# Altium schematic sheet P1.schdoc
size 420 x 297 mm; Symbol: Drawing-Symbol_A4; Company: 嘉立创EDA; Version: V1.0; Page Size: A4; @Project Name: SmartSleeve; @Update Date: 2026-07-03; @Create Date: 2026-07-03; Device: Drawing-Symbol_A4; @Board Name: Board1; @Page Name: P1; @Create Time: 23:50:37; @Page Count: 1; @Page No: 1; @Schematic Name: Schematic1; @Update Time: 23:50:37; @Assembly Variant: Basic; Border: 1; Title Block Position: 3; Size: A4; Width: 1655; Height: 1170; Region Start: 1; X Region Count: 6; Y Region Count: 4; Blade Width: 10
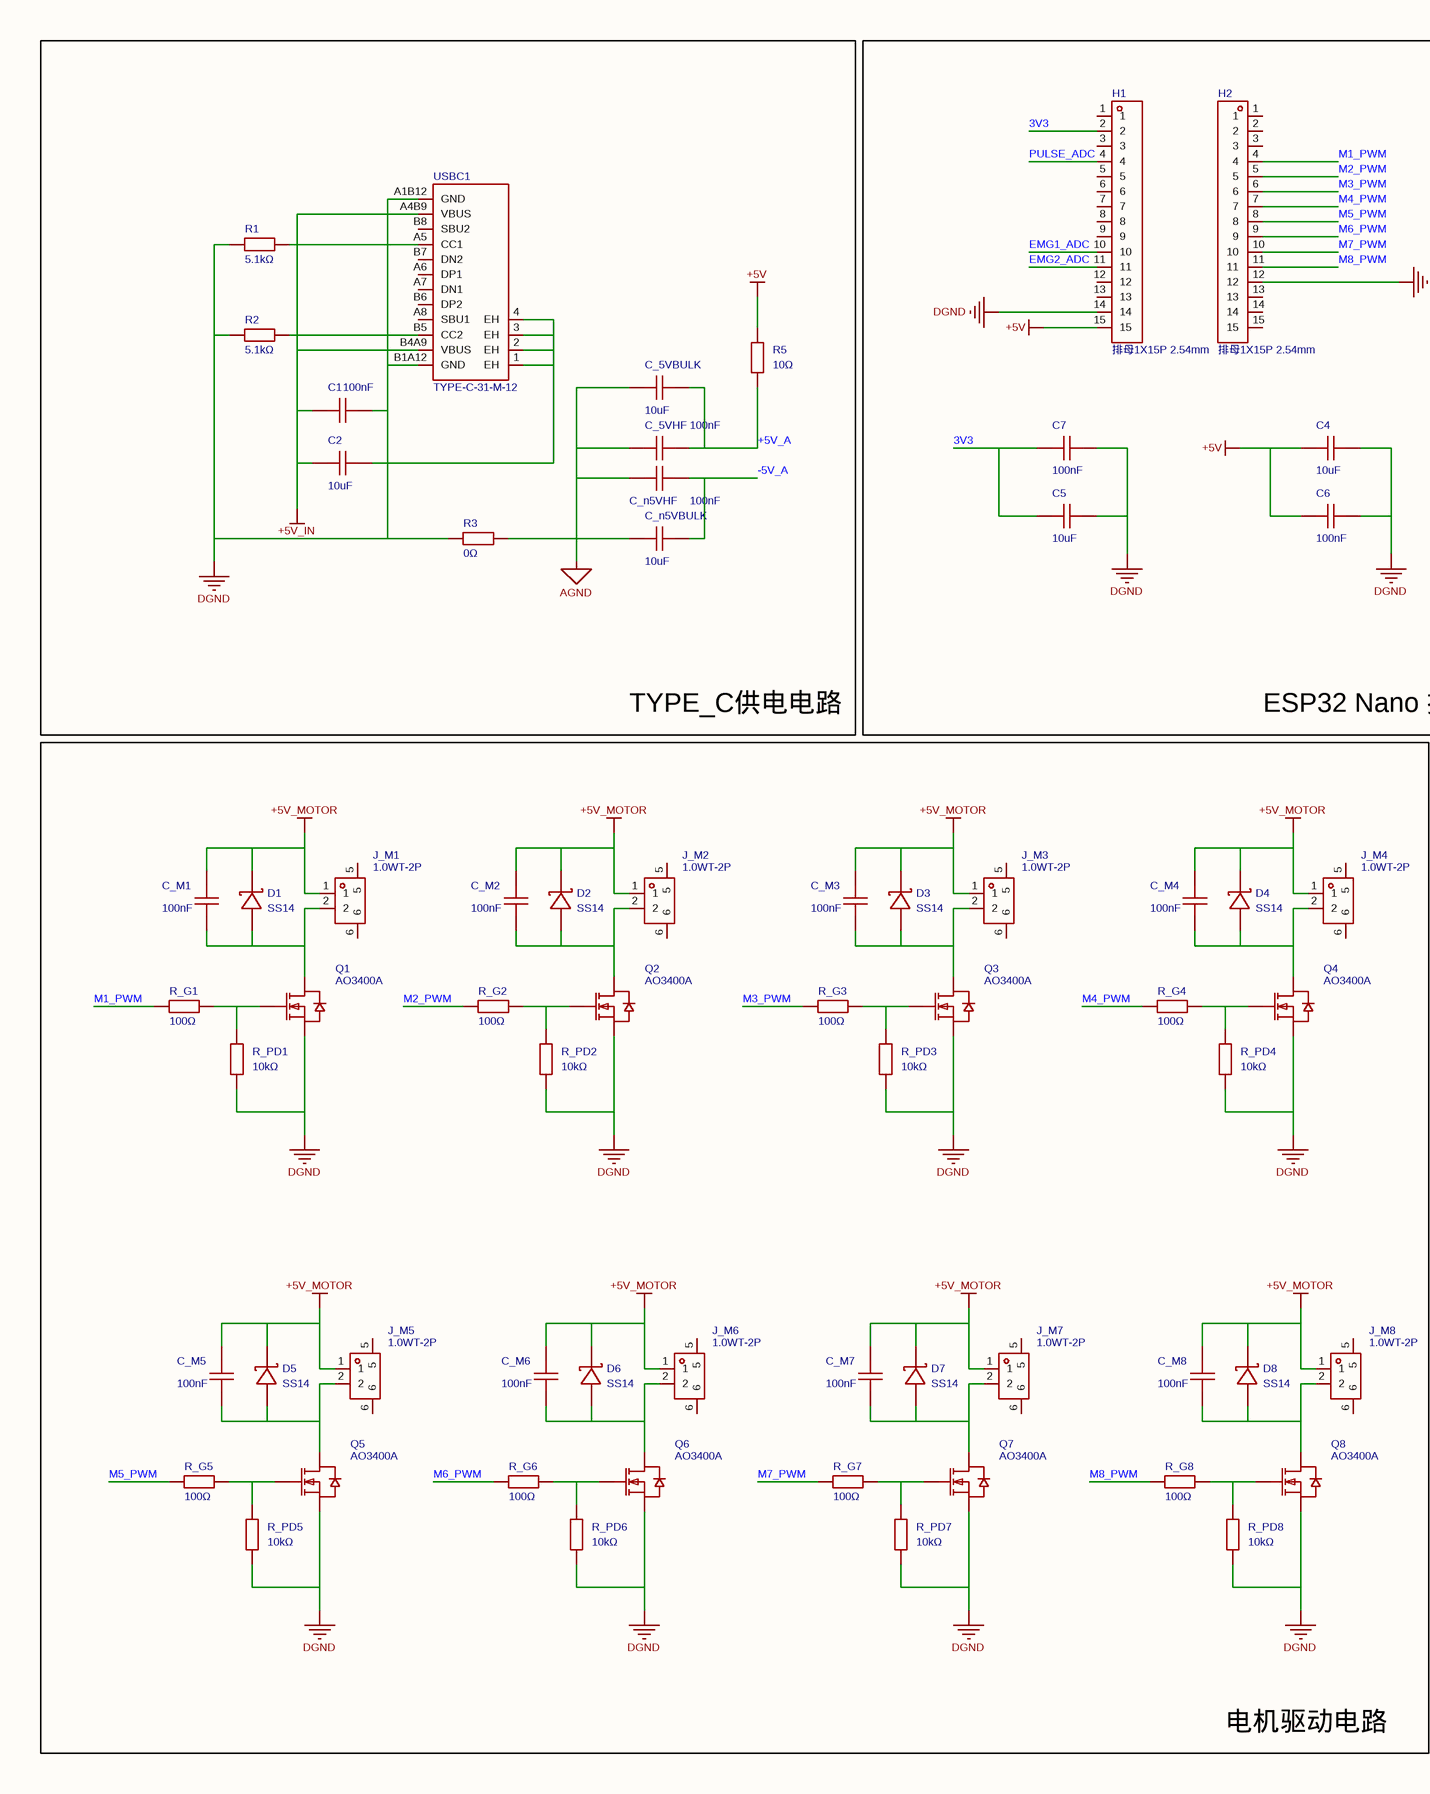
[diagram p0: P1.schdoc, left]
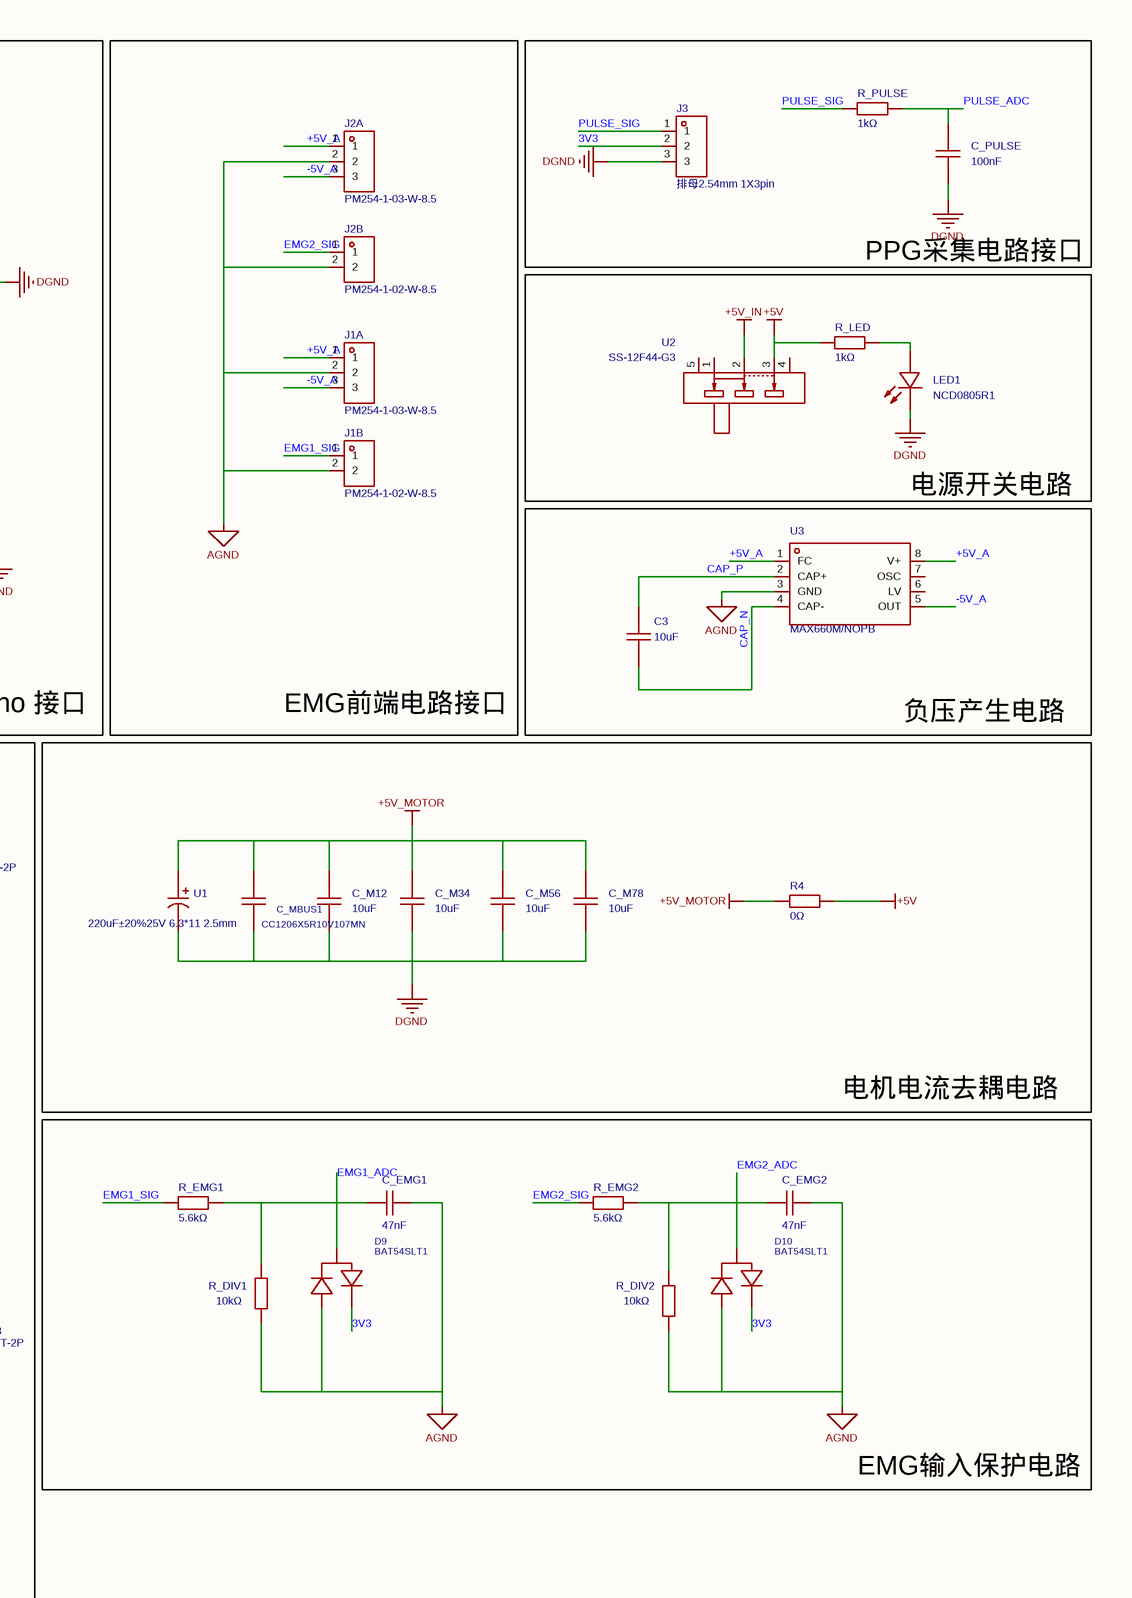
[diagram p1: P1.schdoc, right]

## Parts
C1  100nF  [C0805]
C2  10uF  [C0805]
C3  10uF  [C0805]
C4  10uF  [C0805]
C5  10uF  [C0805]
C6  100nF  [C0805]
C7  100nF  [C0805]
C_5VBULK  10uF  [C0805]
C_5VHF  100nF  [C0805]
C_EMG1  47nF  [C0805]
C_EMG2  47nF  [C0805]
C_M1  100nF  [C0805]
C_M2  100nF  [C0805]
C_M3  100nF  [C0805]
C_M4  100nF  [C0805]
C_M5  100nF  [C0805]
C_M6  100nF  [C0805]
C_M7  100nF  [C0805]
C_M8  100nF  [C0805]
C_M12  10uF  [C0805]
C_M34  10uF  [C0805]
C_M56  10uF  [C0805]
C_M78  10uF  [C0805]
C_MBUS1  CC1206X5R10V107MN  [C1206]
C_n5VBULK  10uF  [C0805]
C_n5VHF  100nF  [C0805]
C_PULSE  100nF  [C0805]
D1  SS14  [SMA_L4.2-W2.6-LS5.0-RD_1]
D2  SS14  [SMA_L4.2-W2.6-LS5.0-RD_1]
D3  SS14  [SMA_L4.2-W2.6-LS5.0-RD_1]
D4  SS14  [SMA_L4.2-W2.6-LS5.0-RD_1]
D5  SS14  [SMA_L4.2-W2.6-LS5.0-RD_1]
D6  SS14  [SMA_L4.2-W2.6-LS5.0-RD_1]
D7  SS14  [SMA_L4.2-W2.6-LS5.0-RD_1]
D8  SS14  [SMA_L4.2-W2.6-LS5.0-RD_1]
D9  BAT54SLT1  [SOT-23-3_L2.9-W1.3-P1.90-LS2.4-BR]
D10  BAT54SLT1  [SOT-23-3_L2.9-W1.3-P1.90-LS2.4-BR]
H1  排母1X15P 2.54mm  [HDR-TH_15P-P2.54-V-F]
H2  排母1X15P 2.54mm  [HDR-TH_15P-P2.54-V-F]
J1A  PM254-1-03-W-8.5  [HDR-TH_3P-P2.54-H-F-W10.0-N]
J1B  PM254-1-02-W-8.5  [HDR-TH_2P-P2.54-H-F-W10.0-N]
J2A  PM254-1-03-W-8.5  [HDR-TH_3P-P2.54-H-F-W10.0-N]
J2B  PM254-1-02-W-8.5  [HDR-TH_2P-P2.54-H-F-W10.0-N]
J3  排母2.54mm 1X3pin  [HDR-TH_3P-P2.54_CS-1165SDIG]
J_M1  1.0WT-2P  [CONN-SMD_2P-P1.00-WT]
J_M2  1.0WT-2P  [CONN-SMD_2P-P1.00-WT]
J_M3  1.0WT-2P  [CONN-SMD_2P-P1.00-WT]
J_M4  1.0WT-2P  [CONN-SMD_2P-P1.00-WT]
J_M5  1.0WT-2P  [CONN-SMD_2P-P1.00-WT]
J_M6  1.0WT-2P  [CONN-SMD_2P-P1.00-WT]
J_M7  1.0WT-2P  [CONN-SMD_2P-P1.00-WT]
J_M8  1.0WT-2P  [CONN-SMD_2P-P1.00-WT]
LED1  NCD0805R1  [LED0805-RD]
Q1  AO3400A  [SOT-23-3_L2.9-W1.3-P1.90-LS2.4-BR]
Q2  AO3400A  [SOT-23-3_L2.9-W1.3-P1.90-LS2.4-BR]
Q3  AO3400A  [SOT-23-3_L2.9-W1.3-P1.90-LS2.4-BR]
Q4  AO3400A  [SOT-23-3_L2.9-W1.3-P1.90-LS2.4-BR]
Q5  AO3400A  [SOT-23-3_L2.9-W1.3-P1.90-LS2.4-BR]
Q6  AO3400A  [SOT-23-3_L2.9-W1.3-P1.90-LS2.4-BR]
Q7  AO3400A  [SOT-23-3_L2.9-W1.3-P1.90-LS2.4-BR]
Q8  AO3400A  [SOT-23-3_L2.9-W1.3-P1.90-LS2.4-BR]
R1  5.1kΩ  [R0805]
R2  5.1kΩ  [R0805]
R3  0Ω  [R0805]
R4  0Ω  [R1206]
R5  10Ω  [R0805_NEW]
R_DIV1  10kΩ  [R0805]
R_DIV2  10kΩ  [R0805]
R_EMG1  5.6kΩ  [R0805]
R_EMG2  5.6kΩ  [R0805]
R_G1  100Ω  [R0805]
R_G2  100Ω  [R0805]
R_G3  100Ω  [R0805]
R_G4  100Ω  [R0805]
R_G5  100Ω  [R0805]
R_G6  100Ω  [R0805]
R_G7  100Ω  [R0805]
R_G8  100Ω  [R0805]
R_LED  1kΩ  [R0805]
R_PD1  10kΩ  [R0805]
R_PD2  10kΩ  [R0805]
R_PD3  10kΩ  [R0805]
R_PD4  10kΩ  [R0805]
R_PD5  10kΩ  [R0805]
R_PD6  10kΩ  [R0805]
R_PD7  10kΩ  [R0805]
R_PD8  10kΩ  [R0805]
R_PULSE  1kΩ  [R0805]
U1  220uF±20%25V 6.3*11 2.5mm  [CAP-TH_BD6.3-P2.50-D0.5-FD]
U2  SS-12F44-G3  [SW-TH_SS-12F44-G5_C2998807]
U3  MAX660M/NOPB  [SOIC-8_L5.0-W4.0-P1.27-LS6.1-BL]
USBC1  TYPE-C-31-M-12  [USB-C_SMD-TYPE-C-31-M-12_1]

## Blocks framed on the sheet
TYPE_C供电电路: C1 C2 C_5VBULK C_5VHF C_n5VBULK C_n5VHF R1-R3 R5 USBC1
ESP32 Nano 接口: C4-C7 H1 H2
EMG前端电路接口: J1A J1B J2A J2B
PPG采集电路接口: C_PULSE J3 R_PULSE
电源开关电路: LED1 R_LED U2
负压产生电路: C3 U3
电机驱动电路: C_M1-C_M8 D1-D8 J_M1-J_M8 Q1-Q8 R_G1-R_G8 R_PD1-R_PD8
电机电流去耦电路: C_M12 C_M34 C_M56 C_M78 C_MBUS1 R4 U1
EMG输入保护电路: C_EMG1 C_EMG2 D9 D10 R_DIV1 R_DIV2 R_EMG1 R_EMG2

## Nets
+5V: C4.1 C6.1 H1.15 R4.2 R5.1 R_LED.2 U2.3
+5V_IN: C1.1 C2.1 U2.2 USBC1.A4B9(VBUS) USBC1.B4A9(VBUS)
+5V_MOTOR: C_M1.2 C_M2.2 C_M3.2 C_M4.2 C_M5.2 C_M6.2 C_M7.2 C_M8.2 C_M12.2 C_M34.2 C_M56.2 C_M78.2 C_MBUS1.2 D1.1(K) D2.1(K) D3.1(K) D4.1(K) D5.1(K) D6.1(K) D7.1(K) D8.1(K) J_M1.1 J_M2.1 J_M3.1 J_M4.1 J_M5.1 J_M6.1 J_M7.1 J_M8.1 R4.1 U1.1
AGND: C_5VBULK.1 C_5VHF.1 C_EMG1.2 C_EMG2.2 C_n5VBULK.1 C_n5VHF.1 D9.1(A) D10.1(A) J1A.2 J1B.2 J2A.2 J2B.2 R3.2 R_DIV1.1 R_DIV2.1 U3.3(GND)
DGND: C1.2 C2.2 C4.2 C5.2 C6.2 C7.2 C_M12.1 C_M34.1 C_M56.1 C_M78.1 C_MBUS1.1 C_PULSE.1 H1.14 H2.12 J3.3 LED1.1(-) Q1.2(S) Q2.2(S) Q3.2(S) Q4.2(S) Q5.2(S) Q6.2(S) Q7.2(S) Q8.2(S) R1.2 R2.1 R3.1 R_PD1.1 R_PD2.1 R_PD3.1 R_PD4.1 R_PD5.1 R_PD6.1 R_PD7.1 R_PD8.1 U1.2 USBC1.1(EH) USBC1.2(EH) USBC1.3(EH) USBC1.4(EH) USBC1.A1B12(GND) USBC1.B1A12(GND)
3V3: C5.1 C7.1 D9.2(C) D10.2(C) H1.2 J3.2
+5V_A: C_5VBULK.2 C_5VHF.2 J1A.1 J2A.1 R5.2 U3.1(FC) U3.8(V+)
-5V_A: C_n5VBULK.2 C_n5VHF.2 J1A.3 J2A.3 U3.5(OUT)
CAP_N: C3.2 U3.4(CAP-)
CAP_P: C3.1 U3.2(CAP+)
EMG1_ADC: C_EMG1.1 D9.3(A/C) H1.10 R_DIV1.2 R_EMG1.2
EMG1_SIG: J1B.1 R_EMG1.1
EMG2_ADC: C_EMG2.1 D10.3(A/C) H1.11 R_DIV2.2 R_EMG2.2
EMG2_SIG: J2B.1 R_EMG2.1
M1_PWM: H2.4 R_G1.1
M2_PWM: H2.5 R_G2.1
M3_PWM: H2.6 R_G3.1
M4_PWM: H2.7 R_G4.1
M5_PWM: H2.8 R_G5.1
M6_PWM: H2.9 R_G6.1
M7_PWM: H2.10 R_G7.1
M8_PWM: H2.11 R_G8.1
PULSE_ADC: C_PULSE.2 H1.4 R_PULSE.2
PULSE_SIG: J3.1 R_PULSE.1
NetC_M1_1: C_M1.1 D1.2(A) J_M1.2 Q1.3(D)
NetC_M2_1: C_M2.1 D2.2(A) J_M2.2 Q2.3(D)
NetC_M3_1: C_M3.1 D3.2(A) J_M3.2 Q3.3(D)
NetC_M4_1: C_M4.1 D4.2(A) J_M4.2 Q4.3(D)
NetC_M5_1: C_M5.1 D5.2(A) J_M5.2 Q5.3(D)
NetC_M6_1: C_M6.1 D6.2(A) J_M6.2 Q6.3(D)
NetC_M7_1: C_M7.1 D7.2(A) J_M7.2 Q7.3(D)
NetC_M8_1: C_M8.1 D8.2(A) J_M8.2 Q8.3(D)
NetLED1_2: LED1.2(+) R_LED.1
NetQ1_1: Q1.1(G) R_G1.2 R_PD1.2
NetQ2_1: Q2.1(G) R_G2.2 R_PD2.2
NetQ3_1: Q3.1(G) R_G3.2 R_PD3.2
NetQ4_1: Q4.1(G) R_G4.2 R_PD4.2
NetQ5_1: Q5.1(G) R_G5.2 R_PD5.2
NetQ6_1: Q6.1(G) R_G6.2 R_PD6.2
NetQ7_1: Q7.1(G) R_G7.2 R_PD7.2
NetQ8_1: Q8.1(G) R_G8.2 R_PD8.2
NetR1_1: R1.1 USBC1.A5(CC1)
NetR2_2: R2.2 USBC1.B5(CC2)

Not connected (* = marked no-connect by the designer): H1 1 3 5 6 7 8 9 12 13; H2 1 2 3 13 14 15; J_M1 5 6; J_M2 5 6; J_M3 5 6; J_M4 5 6; J_M5 5 6; J_M6 5 6; J_M7 5 6; J_M8 5 6; U2 1 4 5; U3 6(LV) 7(OSC); USBC1 A6(DP1) A7(DN1) A8(SBU1) B6(DP2) B7(DN2) B8(SBU2)

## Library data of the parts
C1 = GRM21BR71H104KA01L: 容值:100nF;精度:±10%;额定电压:50V;温度系数:X7R;; Manufacturer: muRata(村田); 3D Model: 1ba041120af144c991958decab20d2410819f05c4eef4c71ace90d822a990e87; 3D Model Transform: 78.74,51.181,0,0,0,0,0,0.0005,0; Tolerance: ±10%; Voltage Rating: 50V; Temperature Coefficient: X7R; AddInBom: yes; ModelName: C0805_L2.0-W1.3-H1.3
C2 = CL21A106KAYNNNE_C15850: 容值:10uF;精度:±10%;额定电压:25V;温度系数:X5R;; Manufacturer: SAMSUNG(三星); Add into BOM: yes; Tolerance: ±10%; Voltage Rating: 25V; Temperature Coefficient: X5R; 3D Model: 1ba041120af144c991958decab20d241; 3D Model Transform: 78.74,51.181,0,0,0,0,0,0.0005,0; ModelName: C0805_L2.0-W1.3-H1.3
C3-C5 C_5VBULK C_M12 C_M34 C_M56 C_M78 C_n5VBULK = CL21A106KAYNNNE_C15850: 容值:10uF;精度:±10%;额定电压:25V;温度系数:X5R;; Manufacturer: SAMSUNG(三星); 3D Model: 1ba041120af144c991958decab20d2410819f05c4eef4c71ace90d822a990e87; 3D Model Transform: 78.74,51.181,0,0,0,0,0,0.0005,0; Tolerance: ±10%; Voltage Rating: 25V; Temperature Coefficient: X5R; AddInBom: yes; ModelName: C0805_L2.0-W1.3-H1.3
C6 C7 C_5VHF C_M1-C_M8 C_n5VHF C_PULSE = CC0805KRX7R9BB104: 容值:100nF;精度:±10%;额定电压:50V;温度系数:X7R;; Manufacturer: YAGEO(国巨); 3D Model: 1ba041120af144c991958decab20d2410819f05c4eef4c71ace90d822a990e87; 3D Model Transform: 78.74,51.181,0,0,0,0,0,0.0005,0; Tolerance: ±10%; Voltage Rating: 50V; Temperature Coefficient: X7R; AddInBom: yes; ModelName: C0805_L2.0-W1.3-H1.3
C_EMG1 C_EMG2 = CL21B473KBCNNNC: 容值:47nF;精度:±10%;额定电压:50V;材质(温度系数):X7R;; Manufacturer: SAMSUNG(三星); AddInBom: yes; ModelId: 1ba041120af144c991958decab20d2410819f05c4eef4c71ace90d822a990e87; ModelName: C0805_L2.0-W1.3-H1.3; ModelTransform: 78.74,51.181,0,0,0,0,0,0.0005,0; Tolerance: ±10%; Voltage Rated: 50V; Temperature Coefficient: X7R
C_MBUS1 = CC1206X5R10V107MN: Manufacturer: TORCH(火炬); AddInBom: yes; ModelId: e4be705b945545a48e666415e3682bd80819f05c4eef4c71ace90d822a990e87; ModelName: C1206_L3.2-W1.6-H1.3; ModelTransform: 125.984,62.992,0,0,0,0,0,0,0
D1-D8 = SS14_C2480: 二极管配置:独立式;正向压降(Vf):550mV@1A;直流反向耐压(Vr):40V;整流电流:1A;; Manufacturer: MDD(辰达半导体); 3D Model: 2ad98c37c5614ad18681cbd22e4725e10819f05c4eef4c71ace90d822a990e87; 3D Model Transform: 196.85,101.181,0,0,0,0,0,0,0; Diode Configuration: 独立式; Voltage - DC Reverse(Vr): 40V; Current - Rectified: 1A; Reverse Leakage Current (Ir): 300uA@40V; Operating Junction Temperature Range: -55℃~+150℃; Non-Repetitive Peak Forward Surge Current: 25A; AddInBom: yes
D9 D10 = BAT54SLT1: 二极管配置:1对串联式;正向压降(Vf):800mV@100mA;直流反向耐压(Vr):30V;整流电流:200mA;; Manufacturer: onsemi(安森美); AddInBom: yes; ModelId: c62791f0466c4ae2a892c056b845b0ca0819f05c4eef4c71ace90d822a990e87; ModelName: SOT-23-3P_L2.9-W1.3-H1.0-LS2.4-P0.95; ModelTransform: 98.425,114.173,0,180,0,0,0.0005,-0.0005,0; Diode Configuration: 1对串联式; Voltage - DC Reverse(Vr): 30V; Current - Rectified: 200mA; Reverse Leakage Current (Ir): 2uA@25V; Operating Junction Temperature Range: -55℃~+150℃; Non-Repetitive Peak Forward Surge Current: 1A
H1 H2 = 排母1X15P 2.54mm: 圆针/方针:-;额定电流:-;额定电压:-;配合针长度:-;塑高:-;触头材质:-;; Symbol: Female header1X15P 2.54mm; 3D Model: 38ff91cb466b435b8c8f2ba8086ca4a00819f05c4eef4c71ace90d822a990e87; 3D Model Transform: 1515.745,98.425,0,0,0,0,0,0,-125.984; AddInBom: yes
J1A J2A = PM254-1-03-W-8.5: 插孔结构:1x3P;间距:2.54mm;行距:-;圆孔/方孔:方孔;安装方式:弯插;排数:单排;总孔位数:3P;额定电流:3A;额定电压:-;插孔方向:侧面;塑高:8.5mm;触头材质:铜合金;工作温度:-40℃~+105℃;; Manufacturer: HCTL(华灿天禄); AddInBom: yes; ModelId: e7d5dbd603a1424b9bba9c909ef70c920819f05c4eef4c71ace90d822a990e87; ModelTransform: 315.7474,399.6055,0,0,0,0,0,-191.22,-125.984; Holes Structure: 1x3P; Pitch: 2.54mm; Circular Hole / Square Hole: 方孔; Number of Positions: 3P; Current Rating: 3A; Holes Direction: 侧面
J1B J2B = PM254-1-02-W-8.5: 插孔结构:1x2P;间距:2.54mm;行距:-;圆孔/方孔:方孔;安装方式:弯插;排数:单排;总孔位数:2P;额定电流:3A;额定电压:-;插孔方向:侧面;塑高:8.5mm;触头材质:铜合金;工作温度:-40℃~+105℃;; Manufacturer: HCTL(华灿天禄); AddInBom: yes; ModelId: a255c5a44f784c7a8d1e9bc183a6e44e0819f05c4eef4c71ace90d822a990e87; ModelTransform: 216.1413,399.6055,0,0,0,0,0,-192.913,-122.047; Holes Structure: 1x2P; Pitch: 2.54mm; Circular Hole / Square Hole: 方孔; Number of Positions: 2P; Current Rating: 3A; Holes Direction: 侧面
J3 = 排母2.54mm 1X3pin: AddInBom: yes; ModelId: 37be19d4eefe45728fb2e34f302d27930819f05c4eef4c71ace90d822a990e87; ModelTransform: 316.141,94.488,0,0,0,0,0,0,-125.984
J_M1-J_M8 = 1.0WT-2P: 3D Model: 0482cc1e6c6742feac0b73b7110cbf730819f05c4eef4c71ace90d822a990e87; 3D Model Transform: 137.795,196.85,0,0,0,0,0,-5.906,0; AddInBom: yes; ModelName: CONN-SMD_SH1.00-WS-2P_1
LED1 = NCD0805R1: 灯头类型:-;发光颜色:红色;正向压降(Vf):1.6V~2.6V;功率:65mW;正向电流:25mA;波长:615nm~630nm;二极管配置:独立二极管;透镜颜色:-;色温:-;发光强度:195mcd;发光角度:130°;载带方式:-;工作温度:-30℃~+85℃;; Manufacturer: 国星光电; Symbol: FC-2012HRK-620D; AddInBom: yes; ModelId: b1c5ed7a4f6e46d3bc6f6cc7c20f3fea0819f05c4eef4c71ace90d822a990e87; ModelTransform: 79.527,49.2125,0,0,0,0,0,0,0; Illumination Color: 红色; Power(Watts): 65mW; Forward Current: 25mA; Peak Wavelength: 630nm; Diode Configuration: 独立二极管; Luminous Intensity: 195mcd; Viewing Angle: 130°
Q1-Q8 = AO3400A_C20917: 数量:-;漏源电压(Vdss):30V;连续漏极电流(Id):-;导通电阻(RDS(on)):48mΩ@2.5V;耗散功率(Pd):-;阈值电压(Vgs(th)):1.45V@250uA;; Manufacturer: AOS; 3D Model: c62791f0466c4ae2a892c056b845b0ca0819f05c4eef4c71ace90d822a990e87; 3D Model Transform: 98.425,114.173,0,180,0,0,0.0005,-0.0005,0; Drain to Source Voltage: 30V; Gate Charge(Qg): 7nC@10V; Input Capacitance(Ciss): 630pF@15V; Type: N沟道; AddInBom: yes; ModelName: SOT-23-3P_L2.9-W1.3-H1.0-LS2.4-P0.95
R1 = FRC0805F5101TS: 电阻类型:厚膜电阻;阻值:5.1kΩ;精度:±1%;功率:125mW;工作电压:150V;温度系数:±100ppm/℃;; Manufacturer: FOJAN(富捷); Add into BOM: yes; Tolerance: ±1%; Power(Watts): 125mW; Voltage-Supply(Max): 150V; 3D Model: 37a81e68749a4138bd2dfa6897b24b850819f05c4eef4c71ace90d822a990e87; 3D Model Transform: 78.74,51.181,0,0,0,0,0,-0.0005,0; Channel ID: $1I4; PCB Layer: TopLayer; ModelName: R0805_L2.0-W1.3-H0.6
R2 = FRC0805F5101TS: 电阻类型:厚膜电阻;阻值:5.1kΩ;精度:±1%;功率:125mW;工作电压:150V;温度系数:±100ppm/℃;; Manufacturer: FOJAN(富捷); Add into BOM: yes; Tolerance: ±1%; Power(Watts): 125mW; Voltage-Supply(Max): 150V; 3D Model: 37a81e68749a4138bd2dfa6897b24b850819f05c4eef4c71ace90d822a990e87; 3D Model Transform: 78.74,51.181,0,0,0,0,0,-0.0005,0; Channel ID: $1I6; PCB Layer: TopLayer; ModelName: R0805_L2.0-W1.3-H0.6
R3 = 0805W8F0000T5E: 电阻类型:厚膜电阻;阻值:0Ω;精度:±1%;功率:125mW;工作电压:150V;温度系数:±800ppm/℃;; Manufacturer: UNI-ROYAL(厚声); Add into BOM: yes; Tolerance: ±1%; Power(Watts): 125mW; Voltage-Supply(Max): 150V; 3D Model: 37a81e68749a4138bd2dfa6897b24b85; 3D Model Transform: 78.74,51.181,0,0,0,0,0,-0.0005,0; ModelName: R0805_L2.0-W1.3-H0.6
R4 = 1206W4F0000T5E: 电阻类型:厚膜电阻;阻值:0Ω;精度:±1%;功率:250mW;工作电压:200V;温度系数:±800ppm/℃;; Manufacturer: UNI-ROYAL(厚声); AddInBom: yes; ModelId: 89a1f13db2384da588040e0b3c55bf660819f05c4eef4c71ace90d822a990e87; ModelName: R1206_L3.2-W1.6-H0.6; ModelTransform: 125.984,62.992,0,0,0,0,0,0,0; Tolerance: ±1%; Power(Watts): 250mW; Voltage-Supply(Max): 200V
R5 = 0805W8F100JT5E: 电阻类型:厚膜电阻;阻值:10Ω;精度:±1%;功率:125mW;工作电压:150V;温度系数:±200ppm/℃;; Manufacturer: UNI-ROYAL(厚声); AddInBom: yes; ModelId: 37a81e68749a4138bd2dfa6897b24b850819f05c4eef4c71ace90d822a990e87; ModelName: R0805_L2.0-W1.3-H0.6; ModelTransform: 78.74,51.181,0,0,0,0,0,-0.0005,0; Tolerance: ±1%; Power(Watts): 125mW; Voltage-Supply(Max): 150V
R_DIV1 R_DIV2 R_PD1-R_PD8 = 0805W8F1002T5E_C17414: 电阻类型:厚膜电阻;阻值:10kΩ;精度:±1%;功率:125mW;工作电压:150V;温度系数:±100ppm/℃;; Manufacturer: UNI-ROYAL(厚声); 3D Model: 37a81e68749a4138bd2dfa6897b24b850819f05c4eef4c71ace90d822a990e87; 3D Model Transform: 78.74,51.181,0,0,0,0,0,-0.0005,0; Tolerance: ±1%; Power(Watts): 125mW; Voltage-Supply(Max): 150V; AddInBom: yes; ModelName: R0805_L2.0-W1.3-H0.6
R_EMG1 R_EMG2 = 0805W8F5601T5E: 电阻类型:厚膜电阻;阻值:5.6kΩ;精度:±1%;功率:125mW;工作电压:150V;温度系数:±100ppm/℃;; Manufacturer: UNI-ROYAL(厚声); AddInBom: yes; ModelId: 37a81e68749a4138bd2dfa6897b24b850819f05c4eef4c71ace90d822a990e87; ModelName: R0805_L2.0-W1.3-H0.6; ModelTransform: 78.74,51.181,0,0,0,0,0,-0.0005,0; Tolerance: ±1%; Power(Watts): 125mW; Voltage-Supply(Max): 150V
R_G1-R_G8 = 0805W8F1000T5E: 电阻类型:厚膜电阻;阻值:100Ω;精度:±1%;功率:125mW;最大工作电压:150V;温度系数:±100ppm/℃;; Manufacturer: UNI-ROYAL(厚声); 3D Model: 37a81e68749a4138bd2dfa6897b24b850819f05c4eef4c71ace90d822a990e87; 3D Model Transform: 78.74,51.181,0,0,0,0,0,-0.0005,0; Tolerance: ±1%; Power(Watts): 125mW; Overload Voltage (Max): 150V; AddInBom: yes; ModelName: R0805_L2.0-W1.3-H0.6
R_LED = 0805W8F1001T5E: 电阻类型:厚膜电阻;阻值:1kΩ;精度:±1%;功率:125mW;最大工作电压:150V;温度系数:±100ppm/℃;; Manufacturer: UNI-ROYAL(厚声); 3D Model: 37a81e68749a4138bd2dfa6897b24b850819f05c4eef4c71ace90d822a990e87; 3D Model Transform: 78.74,51.181,0,0,0,0,0,-0.0005,0; Tolerance: ±1%; Power(Watts): 125mW; Overload Voltage (Max): 150V; AddInBom: yes; ModelName: R0805_L2.0-W1.3-H0.6
R_PULSE = 0805W8F1001T5E: 电阻类型:厚膜电阻;阻值:1kΩ;精度:±1%;功率:125mW;最大工作电压:150V;温度系数:±100ppm/℃;; Manufacturer: UNI-ROYAL(厚声); AddInBom: yes; ModelId: 37a81e68749a4138bd2dfa6897b24b850819f05c4eef4c71ace90d822a990e87; ModelName: R0805_L2.0-W1.3-H0.6; ModelTransform: 78.74,51.181,0,0,0,0,0,-0.0005,0; Tolerance: ±1%; Power(Watts): 125mW; Overload Voltage (Max): 150V
U1 = 220uF±20%25V 6.3*11 2.5mm: AddInBom: yes; ModelId: 983aa343eddc42b59ebb10541a88166e0819f05c4eef4c71ace90d822a990e87; ModelTransform: 247.99486,248.229,0,90,0,0,0,0,-196.85
U2 = SS-12F44-G3_C7506805: 滑动开关  滑动开关; Manufacturer: DEALON(德艺隆); AddInBom: yes; ModelId: f813f725b6324f2f952e8c628d74c1d80819f05c4eef4c71ace90d822a990e87; ModelTransform: 480.314,232.283,0,0,0,0,0,0,-118.11
U3 = MAX660M/NOPB: MAX660 10kHz/80kHz 开关电容器电压转换器; Manufacturer: TI(德州仪器); AddInBom: yes; ModelId: e95f26ea62414da0907e5731acbf3c9b0819f05c4eef4c71ace90d822a990e87; ModelTransform: 192.913,236.22,0,0,0,0,0,0,0
USBC1 = TYPE-C-31-M-12: 连接器类型:Type-C;协议标准:-;公母:母;安装方式:卧贴;触点数量:16P;端口数量:1;额定电流 - 电源:5A;工作温度:-30℃~+80℃;; Manufacturer: 韩国韩荣; Add into BOM: yes; Connector Type: Type-C; Gender: 母; Number of Contacts: 16P; Number of Ports: 1; Current Rating-Power: 5A; Voltage Rating: 20V; Connect-Disconnect Life: 1万次; 3D Model: 2a22bb5af8894b85972aeeacf9cd92d00819f05c4eef4c71ace90d822a990e87; 3D Model Transform: 351.9678,311.023,0,180,0,0,0,-43.307,-33.465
